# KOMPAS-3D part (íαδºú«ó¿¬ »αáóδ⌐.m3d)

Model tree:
1. Эскиз:1
2. Операция выдавливания:1
     Расстояние 1 = 39; Расстояние 2 = 1
3. Эскиз:2
4. Вырезать элемент выдавливания:1
     Расстояние 1 = 45
5. Эскиз:3
6. Операция выдавливания:2
     Расстояние 1 = 6.3; Расстояние 2 = 1
7. Скругление:6
     Радиус = 1
8. Эскиз:10
9. Вырезать элемент выдавливания:8
     Расстояние 1 = 5
10. Эскиз:13
11. Операция выдавливания:4
     Расстояние 1 = 0.5
12. Скругление:13
     Радиус = 0.5
13. Эскиз:15
14. Вырезать элемент выдавливания:11
     Расстояние 1 = 45
15. Фаска:3
     Угол = 45; Длина 1 = 4; Длина 2 = 4
16. Сплайновая форма:2
17. Скругление:15
     Радиус = 2
18. Скругление:16
     Радиус = 2
19. Скругление:18
     Радиус = 2
20. Скругление:19
     Радиус = 2
21. Эскиз:18
22. Вырезать элемент выдавливания:14
     Расстояние 1 = 30; Угол 1 = 11
23. Эскиз:19
24. Вырезать элемент выдавливания:15
     Расстояние 1 = 12; Угол 1 = 22
25. Эскиз:20
26. Вырезать элемент выдавливания:16
     Расстояние 1 = 4; Угол 1 = 22
27. Эскиз:21
28. Операция выдавливания:5
     Расстояние 1 = 50
29. Эскиз:23
30. Вырезать элемент выдавливания:17
     Расстояние 2 = 6; Расстояние 1 = 4
31. Скругление:20
     Радиус = 2
32. Зеркальное отражение:1

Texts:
  Сплав АЛ8  ГОСТ 1583-93
  stalker61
